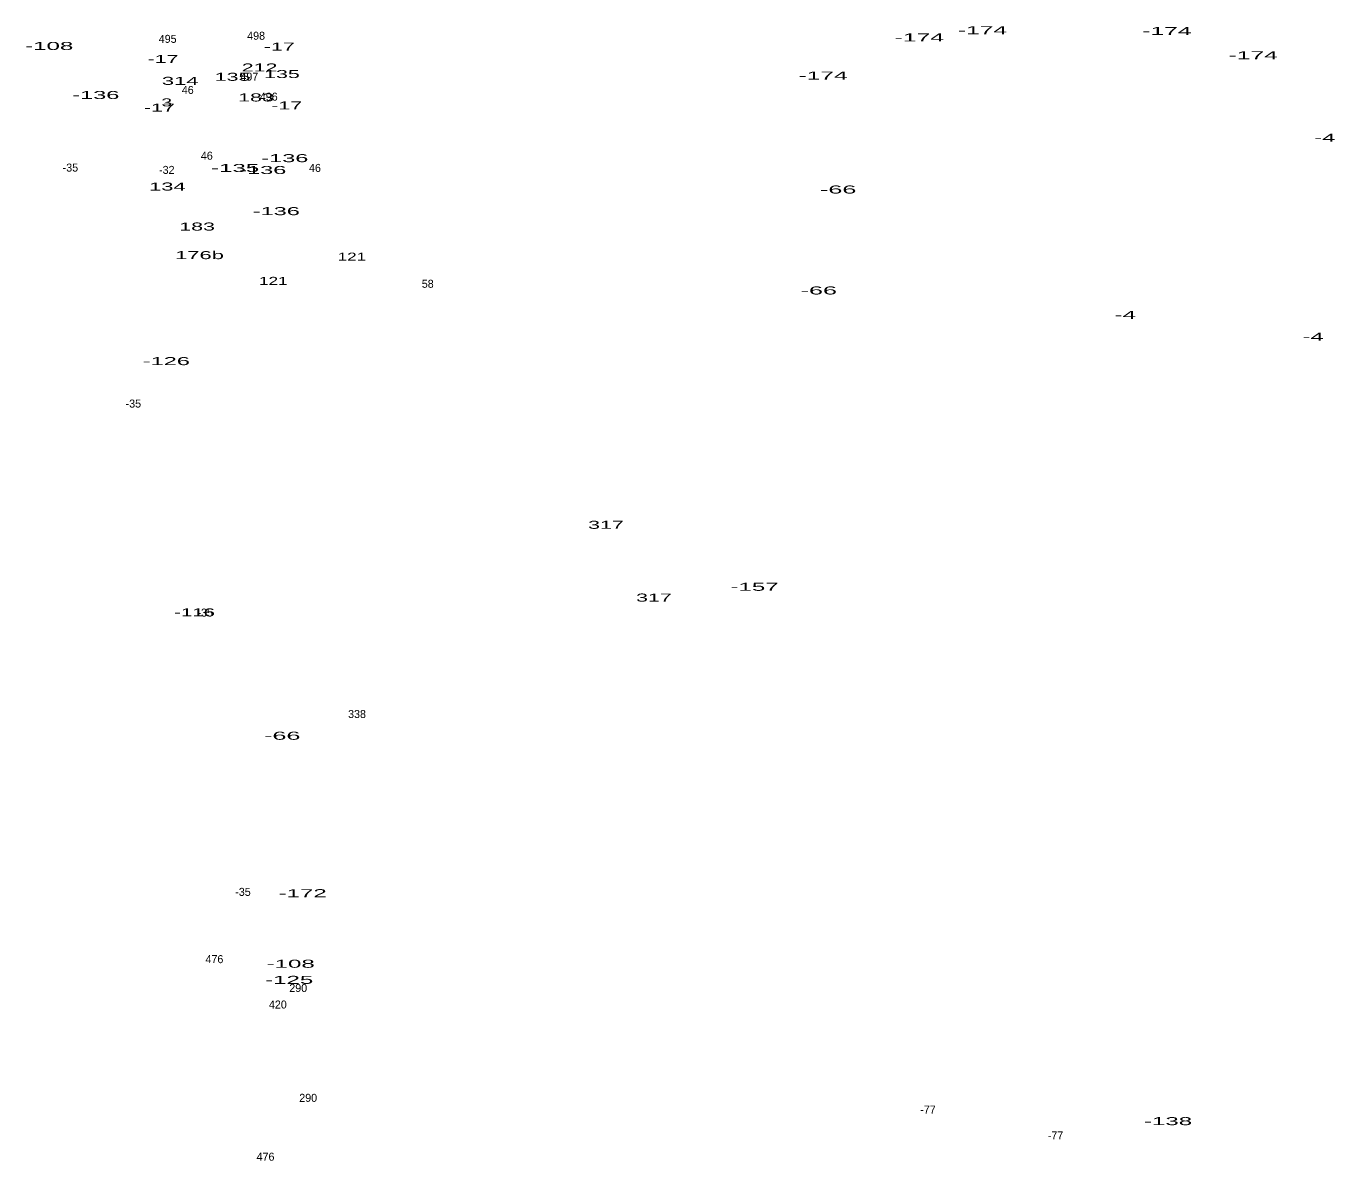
# Model space of a CAD drawing. Extents: x -662280 to -658689, y -991723 to -987042.
# Drawn here: x -661548 to -660894, y -991141 to -990574 of the extents above; entities that cross this region are included whole.
import ezdxf
from ezdxf.enums import TextEntityAlignment as Align

# ---------------------------------------------------------------- set-up
doc = ezdxf.new("R2010")
doc.units = 0
doc.header["$LTSCALE"] = 1.6
doc.layers.add('24', color=7, linetype='Continuous')

msp = doc.modelspace()

# ---------------------------------------------------------------- texts
at = {"layer": '24'}
for s, width, p in [('-174', 2.3, (-661070.411, -990578.26)), ('-174', 2.3, (-660978.241, -990578.67)), ('-174', 2.3, (-661101.941, -990581.9)), ('-108', 2.25, (-661536.747, -990586.15)), ('-17', 2, (-661421.785, -990586.47)), ('-174', 2.3, (-660935.111, -990590.8)), ('-17', 2, (-661479.875, -990592.65)), ('212', 2, (-661431.637, -990596.91)), ('314', 2.05, (-661471.283, -990603.59)), ('135', 2, (-661445.127, -990601.56)), ('135', 2, (-661420.447, -990600.18)), ('-174', 2.3, (-661150.051, -990600.92)), ('-136', 2.2, (-661513.465, -990610.65)), ('183', 2, (-661433.417, -990611.86)), ('-17', 2, (-661481.695, -990616.95)), ('3', 1.8, (-661478.011, -990614.34)), ('-17', 2, (-661418.045, -990615.84)), ('-4', 2.25, (-660899.34, -990632.03)), ('-136', 2.2, (-661419.025, -990642.21)), ('-135', 2.25, (-661443.851, -990647.13)), ('-136', 2.2, (-661430.035, -990648.14)), ('134', 2.05, (-661477.683, -990656.39)), ('-66', 2.35, (-661142.503, -990657.89)), ('-136', 2.2, (-661423.265, -990668.7)), ('183', 2, (-661462.837, -990676.39)), ('176b', 2.05, (-661461.642, -990690.67)), ('121', 1.6, (-661385.494, -990691.43)), ('121', 1.6, (-661424.744, -990703.53)), ('-66', 2.35, (-661152.183, -990708.33)), ('-4', 2.25, (-660999.09, -990720.57)), ('-4', 2.25, (-660905.17, -990731.45)), ('-126', 2.2, (-661478.215, -990743.63)), ('317', 2, (-661258.553, -990825.43)), ('-157', 2.25, (-661184.285, -990856.4)), ('317', 2, (-661234.583, -990861.8)), ('-116', 1.9, (-661464.101, -990869.18)), ('-66', 2.35, (-661420.293, -990930.84)), ('-172', 2.25, (-661410.095, -991009.51)), ('-108', 2.25, (-661416.087, -991044.77)), ('-125', 2.25, (-661416.821, -991052.83)), ('-138', 2.25, (-660977.681, -991123.43))]:
    msp.add_text(s, height=4, dxfattribs=dict(at, width=width)).set_placement(p, align=Align.CENTER)
for s, p in [('495', (-661477.547, -990582.6)), ('498', (-661433.367, -990581.05)), ('497', (-661436.733, -990601.49)), ('46', (-661467.517, -990608.13)), ('496', (-661427.043, -990611.49)), ('46', (-661457.987, -990640.98)), ('-35', (-661526.155, -990646.93)), ('-32', (-661477.985, -990648.08)), ('46', (-661403.967, -990647.09)), ('58', (-661347.607, -990704.99)), ('-35', (-661494.705, -990764.85)), ('-35', (-661458.795, -990869.3)), ('338', (-661382.937, -990919.98)), ('-35', (-661439.925, -991008.86)), ('476', (-661454.193, -991042.47)), ('290', (-661412.317, -991056.89)), ('420', (-661422.495, -991065.15)), ('290', (-661407.337, -991111.78)), ('-77', (-661097.645, -991117.67)), ('-77', (-661033.925, -991130.58)), ('476', (-661428.663, -991141.2))]:
    msp.add_text(s, height=4, dxfattribs=at).set_placement(p, align=Align.CENTER)

doc.saveas('drawing.dxf')
